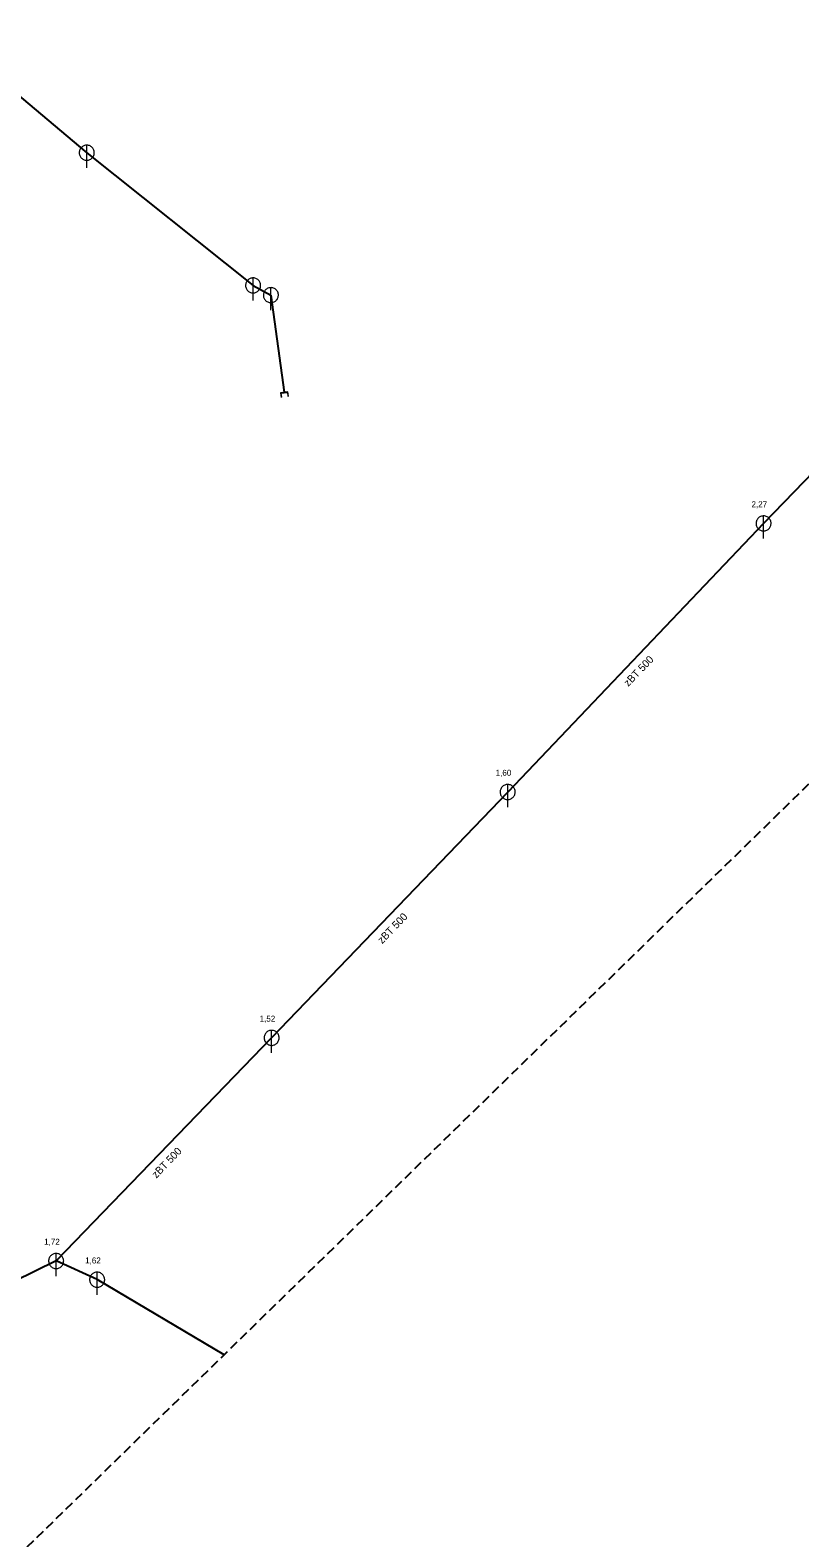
# Model space of a CAD drawing. Extents: x -724334 to -723692, y -972150 to -970648.
# Drawn here: x -724005.6 to -723903.3, y -971004.7 to -970804.3 of the extents above; entities that cross this region are included whole.
import ezdxf

# ---------------------------------------------------------------- set-up
doc = ezdxf.new("R2010")
doc.units = 0
doc.header["$LTSCALE"] = 0.4
doc.linetypes.add('MEDIUM_DASHED', pattern=[4.5, 3, -1.5])
for name, color, linetype, lineweight in [('1', 7, 'Continuous', 25), ('14', 7, 'Continuous', 25), ('22', 7, 'Continuous', 13), ('29', 7, 'Continuous', 13)]:
    doc.layers.add(name, color=color, linetype=linetype, lineweight=lineweight)

msp = doc.modelspace()

# ---------------------------------------------------------------- linework, layer by layer
at = {"layer": '1', "linetype": 'MEDIUM_DASHED'}
msp.add_lwpolyline([(-723848.074, -970648.428), (-723714.095, -970720.999), (-724065.788, -971064.318), (-723792.249, -971201.088), (-723702.93, -971508.122), (-723691.766, -972150.101), (-723842.491, -972097.068), (-723864.821, -971424.385), (-723982.052, -971259.703), (-724333.745, -971117.352)], close=True, dxfattribs=at)
at = {"layer": '14'}
for p, q in [((-724013.248, -970807.906), (-723998.093, -970820.63)), ((-723998.093, -970820.63), (-723975.99, -970838.27)), ((-723975.99, -970838.27), (-723973.62, -970839.57)), ((-723973.62, -970839.57), (-723971.849, -970852.479)), ((-723887.84, -970848.91), (-723908.14, -970869.91)), ((-723908.14, -970869.91), (-723942.149, -970905.61)), ((-723942.149, -970905.61), (-723973.52, -970938.289)), ((-723973.52, -970938.289), (-724002.16, -970967.949)), ((-723996.71, -970970.43), (-724002.16, -970967.949)), ((-723979.846, -970980.423), (-723996.71, -970970.43))]:
    msp.add_line(p, q, dxfattribs=at)
msp.add_lwpolyline([(-724002.16, -970967.949), (-724038.379, -970985.76), (-724040.368, -970986.355)], dxfattribs=at)
at = {"layer": '22'}
for p, q in [((-723998.092, -970822.629), (-723998.091, -970819.629)), ((-723975.989, -970840.27), (-723975.988, -970837.27)), ((-723973.62, -970841.57), (-723973.619, -970838.57)), ((-723908.14, -970871.91), (-723908.139, -970868.91)), ((-723942.149, -970907.61), (-723942.148, -970904.61)), ((-723973.52, -970940.289), (-723973.519, -970937.289)), ((-724002.16, -970969.949), (-724002.159, -970966.949)), ((-723996.71, -970972.43), (-723996.709, -970969.43))]:
    msp.add_line(p, q, dxfattribs=at)
for points in [[(-723997.092, -970820.629), (-723997.097, -970820.52), (-723997.115, -970820.412), (-723997.145, -970820.306), (-723997.185, -970820.205), (-723997.237, -970820.108), (-723997.299, -970820.018), (-723997.371, -970819.935), (-723997.451, -970819.861), (-723997.539, -970819.795), (-723997.633, -970819.74), (-723997.733, -970819.695), (-723997.838, -970819.662), (-723997.945, -970819.64), (-723998.054, -970819.63), (-723998.164, -970819.632), (-723998.272, -970819.646), (-723998.379, -970819.671), (-723998.482, -970819.708), (-723998.58, -970819.757), (-723998.672, -970819.815), (-723998.758, -970819.884), (-723998.835, -970819.961), (-723998.904, -970820.047), (-723998.963, -970820.139), (-723999.011, -970820.237), (-723999.048, -970820.34), (-723999.074, -970820.447), (-723999.088, -970820.555), (-723999.091, -970820.665), (-723999.081, -970820.774), (-723999.06, -970820.881), (-723999.026, -970820.985), (-723998.982, -970821.085), (-723998.927, -970821.18), (-723998.861, -970821.268), (-723998.787, -970821.348), (-723998.704, -970821.42), (-723998.614, -970821.482), (-723998.518, -970821.534), (-723998.416, -970821.575), (-723998.311, -970821.605), (-723998.203, -970821.623), (-723998.093, -970821.629), (-723997.984, -970821.623), (-723997.876, -970821.605), (-723997.771, -970821.576), (-723997.669, -970821.535), (-723997.572, -970821.483), (-723997.482, -970821.421), (-723997.399, -970821.35), (-723997.324, -970821.27), (-723997.259, -970821.182), (-723997.203, -970821.088), (-723997.159, -970820.988), (-723997.125, -970820.884), (-723997.103, -970820.776), (-723997.093, -970820.667)], [(-723974.989, -970838.27), (-723974.994, -970838.161), (-723975.012, -970838.053), (-723975.042, -970837.947), (-723975.082, -970837.846), (-723975.134, -970837.749), (-723975.196, -970837.659), (-723975.268, -970837.576), (-723975.348, -970837.502), (-723975.436, -970837.436), (-723975.53, -970837.381), (-723975.63, -970837.336), (-723975.735, -970837.303), (-723975.842, -970837.281), (-723975.951, -970837.271), (-723976.061, -970837.273), (-723976.169, -970837.287), (-723976.276, -970837.312), (-723976.379, -970837.349), (-723976.477, -970837.398), (-723976.569, -970837.456), (-723976.655, -970837.525), (-723976.732, -970837.602), (-723976.801, -970837.688), (-723976.86, -970837.78), (-723976.908, -970837.878), (-723976.945, -970837.981), (-723976.971, -970838.088), (-723976.985, -970838.196), (-723976.988, -970838.306), (-723976.978, -970838.415), (-723976.957, -970838.522), (-723976.923, -970838.626), (-723976.879, -970838.726), (-723976.824, -970838.821), (-723976.758, -970838.909), (-723976.684, -970838.989), (-723976.601, -970839.061), (-723976.511, -970839.123), (-723976.415, -970839.175), (-723976.313, -970839.216), (-723976.208, -970839.246), (-723976.1, -970839.264), (-723975.99, -970839.27), (-723975.881, -970839.264), (-723975.773, -970839.246), (-723975.668, -970839.217), (-723975.566, -970839.176), (-723975.469, -970839.124), (-723975.379, -970839.062), (-723975.296, -970838.991), (-723975.221, -970838.911), (-723975.156, -970838.823), (-723975.1, -970838.729), (-723975.056, -970838.629), (-723975.022, -970838.525), (-723975, -970838.417), (-723974.99, -970838.308)], [(-723972.62, -970839.57), (-723972.625, -970839.461), (-723972.643, -970839.353), (-723972.673, -970839.247), (-723972.713, -970839.146), (-723972.765, -970839.049), (-723972.827, -970838.959), (-723972.899, -970838.876), (-723972.979, -970838.802), (-723973.067, -970838.736), (-723973.161, -970838.681), (-723973.261, -970838.636), (-723973.366, -970838.603), (-723973.473, -970838.581), (-723973.582, -970838.571), (-723973.692, -970838.573), (-723973.8, -970838.587), (-723973.907, -970838.612), (-723974.01, -970838.649), (-723974.108, -970838.698), (-723974.2, -970838.756), (-723974.286, -970838.825), (-723974.363, -970838.902), (-723974.432, -970838.988), (-723974.491, -970839.08), (-723974.539, -970839.178), (-723974.576, -970839.281), (-723974.602, -970839.388), (-723974.616, -970839.496), (-723974.619, -970839.606), (-723974.609, -970839.715), (-723974.588, -970839.822), (-723974.554, -970839.926), (-723974.51, -970840.026), (-723974.455, -970840.121), (-723974.389, -970840.209), (-723974.315, -970840.289), (-723974.232, -970840.361), (-723974.142, -970840.423), (-723974.046, -970840.475), (-723973.944, -970840.516), (-723973.839, -970840.546), (-723973.731, -970840.564), (-723973.621, -970840.57), (-723973.512, -970840.564), (-723973.404, -970840.546), (-723973.299, -970840.517), (-723973.197, -970840.476), (-723973.1, -970840.424), (-723973.01, -970840.362), (-723972.927, -970840.291), (-723972.852, -970840.211), (-723972.787, -970840.123), (-723972.731, -970840.029), (-723972.687, -970839.929), (-723972.653, -970839.825), (-723972.631, -970839.717), (-723972.621, -970839.608)], [(-723907.14, -970869.91), (-723907.145, -970869.801), (-723907.163, -970869.693), (-723907.193, -970869.587), (-723907.233, -970869.486), (-723907.285, -970869.389), (-723907.347, -970869.299), (-723907.419, -970869.216), (-723907.499, -970869.142), (-723907.587, -970869.076), (-723907.681, -970869.021), (-723907.781, -970868.976), (-723907.886, -970868.943), (-723907.993, -970868.921), (-723908.102, -970868.911), (-723908.212, -970868.913), (-723908.32, -970868.927), (-723908.427, -970868.952), (-723908.53, -970868.989), (-723908.628, -970869.038), (-723908.72, -970869.096), (-723908.806, -970869.165), (-723908.883, -970869.242), (-723908.952, -970869.328), (-723909.011, -970869.42), (-723909.059, -970869.518), (-723909.096, -970869.621), (-723909.122, -970869.728), (-723909.136, -970869.836), (-723909.139, -970869.946), (-723909.129, -970870.055), (-723909.108, -970870.162), (-723909.074, -970870.266), (-723909.03, -970870.366), (-723908.975, -970870.461), (-723908.909, -970870.549), (-723908.835, -970870.629), (-723908.752, -970870.701), (-723908.662, -970870.763), (-723908.566, -970870.815), (-723908.464, -970870.856), (-723908.359, -970870.886), (-723908.251, -970870.904), (-723908.141, -970870.91), (-723908.032, -970870.904), (-723907.924, -970870.886), (-723907.819, -970870.857), (-723907.717, -970870.816), (-723907.62, -970870.764), (-723907.53, -970870.702), (-723907.447, -970870.631), (-723907.372, -970870.551), (-723907.307, -970870.463), (-723907.251, -970870.369), (-723907.207, -970870.269), (-723907.173, -970870.165), (-723907.151, -970870.057), (-723907.141, -970869.948)], [(-723941.149, -970905.61), (-723941.154, -970905.501), (-723941.172, -970905.393), (-723941.202, -970905.287), (-723941.242, -970905.186), (-723941.294, -970905.089), (-723941.356, -970904.999), (-723941.428, -970904.916), (-723941.508, -970904.842), (-723941.596, -970904.776), (-723941.69, -970904.721), (-723941.79, -970904.676), (-723941.895, -970904.643), (-723942.002, -970904.621), (-723942.111, -970904.611), (-723942.221, -970904.613), (-723942.329, -970904.627), (-723942.436, -970904.652), (-723942.539, -970904.689), (-723942.637, -970904.738), (-723942.729, -970904.796), (-723942.815, -970904.865), (-723942.892, -970904.942), (-723942.961, -970905.028), (-723943.02, -970905.12), (-723943.068, -970905.218), (-723943.105, -970905.321), (-723943.131, -970905.428), (-723943.145, -970905.536), (-723943.148, -970905.646), (-723943.138, -970905.755), (-723943.117, -970905.862), (-723943.083, -970905.966), (-723943.039, -970906.066), (-723942.984, -970906.161), (-723942.918, -970906.249), (-723942.844, -970906.329), (-723942.761, -970906.401), (-723942.671, -970906.463), (-723942.575, -970906.515), (-723942.473, -970906.556), (-723942.368, -970906.586), (-723942.26, -970906.604), (-723942.15, -970906.61), (-723942.041, -970906.604), (-723941.933, -970906.586), (-723941.828, -970906.557), (-723941.726, -970906.516), (-723941.629, -970906.464), (-723941.539, -970906.402), (-723941.456, -970906.331), (-723941.381, -970906.251), (-723941.316, -970906.163), (-723941.26, -970906.069), (-723941.216, -970905.969), (-723941.182, -970905.865), (-723941.16, -970905.757), (-723941.15, -970905.648)], [(-723972.52, -970938.289), (-723972.525, -970938.18), (-723972.543, -970938.072), (-723972.573, -970937.966), (-723972.613, -970937.865), (-723972.665, -970937.768), (-723972.727, -970937.678), (-723972.799, -970937.595), (-723972.879, -970937.521), (-723972.967, -970937.455), (-723973.061, -970937.4), (-723973.161, -970937.355), (-723973.266, -970937.322), (-723973.373, -970937.3), (-723973.482, -970937.29), (-723973.592, -970937.292), (-723973.7, -970937.306), (-723973.807, -970937.331), (-723973.91, -970937.368), (-723974.008, -970937.417), (-723974.1, -970937.475), (-723974.186, -970937.544), (-723974.263, -970937.621), (-723974.332, -970937.707), (-723974.391, -970937.799), (-723974.439, -970937.897), (-723974.476, -970938), (-723974.502, -970938.107), (-723974.516, -970938.215), (-723974.519, -970938.325), (-723974.509, -970938.434), (-723974.488, -970938.541), (-723974.454, -970938.645), (-723974.41, -970938.745), (-723974.355, -970938.84), (-723974.289, -970938.928), (-723974.215, -970939.008), (-723974.132, -970939.08), (-723974.042, -970939.142), (-723973.946, -970939.194), (-723973.844, -970939.235), (-723973.739, -970939.265), (-723973.631, -970939.283), (-723973.521, -970939.289), (-723973.412, -970939.283), (-723973.304, -970939.265), (-723973.199, -970939.236), (-723973.097, -970939.195), (-723973, -970939.143), (-723972.91, -970939.081), (-723972.827, -970939.01), (-723972.752, -970938.93), (-723972.687, -970938.842), (-723972.631, -970938.748), (-723972.587, -970938.648), (-723972.553, -970938.544), (-723972.531, -970938.436), (-723972.521, -970938.327)], [(-724001.16, -970967.949), (-724001.165, -970967.84), (-724001.183, -970967.732), (-724001.213, -970967.626), (-724001.253, -970967.525), (-724001.305, -970967.428), (-724001.367, -970967.338), (-724001.439, -970967.255), (-724001.519, -970967.181), (-724001.607, -970967.115), (-724001.701, -970967.06), (-724001.801, -970967.015), (-724001.906, -970966.982), (-724002.013, -970966.96), (-724002.122, -970966.95), (-724002.232, -970966.952), (-724002.34, -970966.966), (-724002.447, -970966.991), (-724002.55, -970967.028), (-724002.648, -970967.077), (-724002.74, -970967.135), (-724002.826, -970967.204), (-724002.903, -970967.281), (-724002.972, -970967.367), (-724003.031, -970967.459), (-724003.079, -970967.557), (-724003.116, -970967.66), (-724003.142, -970967.767), (-724003.156, -970967.875), (-724003.159, -970967.985), (-724003.149, -970968.094), (-724003.128, -970968.201), (-724003.094, -970968.305), (-724003.05, -970968.405), (-724002.995, -970968.5), (-724002.929, -970968.588), (-724002.855, -970968.668), (-724002.772, -970968.74), (-724002.682, -970968.802), (-724002.586, -970968.854), (-724002.484, -970968.895), (-724002.379, -970968.925), (-724002.271, -970968.943), (-724002.161, -970968.949), (-724002.052, -970968.943), (-724001.944, -970968.925), (-724001.839, -970968.896), (-724001.737, -970968.855), (-724001.64, -970968.803), (-724001.55, -970968.741), (-724001.467, -970968.67), (-724001.392, -970968.59), (-724001.327, -970968.502), (-724001.271, -970968.408), (-724001.227, -970968.308), (-724001.193, -970968.204), (-724001.171, -970968.096), (-724001.161, -970967.987)], [(-723995.71, -970970.43), (-723995.715, -970970.321), (-723995.733, -970970.213), (-723995.763, -970970.107), (-723995.803, -970970.006), (-723995.855, -970969.909), (-723995.917, -970969.819), (-723995.989, -970969.736), (-723996.069, -970969.662), (-723996.157, -970969.596), (-723996.251, -970969.541), (-723996.351, -970969.496), (-723996.456, -970969.463), (-723996.563, -970969.441), (-723996.672, -970969.431), (-723996.782, -970969.433), (-723996.89, -970969.447), (-723996.997, -970969.472), (-723997.1, -970969.509), (-723997.198, -970969.558), (-723997.29, -970969.616), (-723997.376, -970969.685), (-723997.453, -970969.762), (-723997.522, -970969.848), (-723997.581, -970969.94), (-723997.629, -970970.038), (-723997.666, -970970.141), (-723997.692, -970970.248), (-723997.706, -970970.356), (-723997.709, -970970.466), (-723997.699, -970970.575), (-723997.678, -970970.682), (-723997.644, -970970.786), (-723997.6, -970970.886), (-723997.545, -970970.981), (-723997.479, -970971.069), (-723997.405, -970971.149), (-723997.322, -970971.221), (-723997.232, -970971.283), (-723997.136, -970971.335), (-723997.034, -970971.376), (-723996.929, -970971.406), (-723996.821, -970971.424), (-723996.711, -970971.43), (-723996.602, -970971.424), (-723996.494, -970971.406), (-723996.389, -970971.377), (-723996.287, -970971.336), (-723996.19, -970971.284), (-723996.1, -970971.222), (-723996.017, -970971.151), (-723995.942, -970971.071), (-723995.877, -970970.983), (-723995.821, -970970.889), (-723995.777, -970970.789), (-723995.743, -970970.685), (-723995.721, -970970.577), (-723995.711, -970970.468)]]:
    msp.add_lwpolyline(points, close=True, dxfattribs=at)
at = {"layer": '29'}
for points in [[(-723971.281, -970853.037), (-723971.356, -970852.42), (-723972.341, -970852.538), (-723972.266, -970853.156)], [(-723972.18, -970853.145), (-723972.244, -970852.614), (-723971.432, -970852.517), (-723971.369, -970853.048)]]:
    msp.add_lwpolyline(points, dxfattribs=at)

# ---------------------------------------------------------------- texts
at = {"layer": '1'}
for s, p in [('2,27', (-723909.74, -970867.757)), ('1,60', (-723943.75, -970903.457)), ('1,52', (-723975.119, -970936.137)), ('1,72', (-724003.76, -970965.797)), ('1,62', (-723998.31, -970968.277))]:
    msp.add_text(s, height=0.8, dxfattribs=at).set_placement(p)
for p in [(-723926.121, -970891.663), (-723958.826, -970925.849), (-723988.842, -970957.016)]:
    msp.add_text('zBT 500 ', height=1, rotation=46, dxfattribs=at).set_placement(p)

doc.saveas('drawing.dxf')
